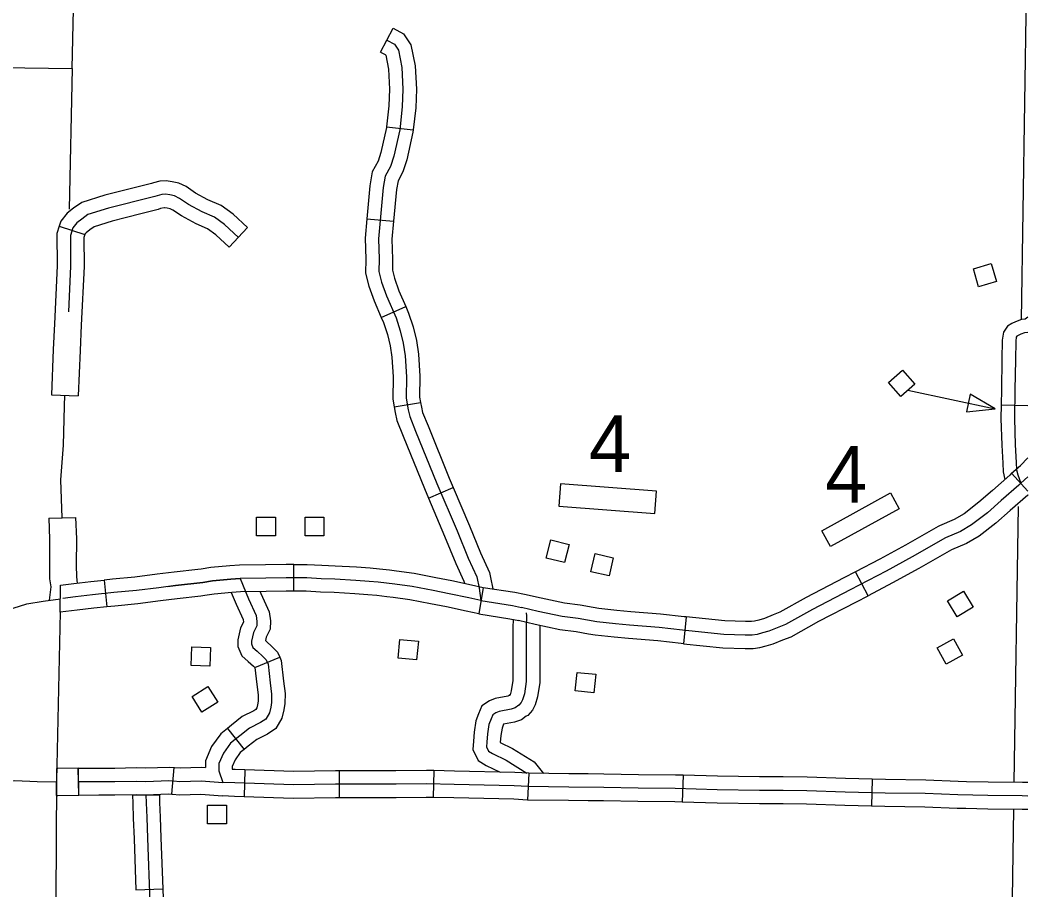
# Model space of a CAD drawing. Extents: x 61396 to 64680, y 55472 to 57605.
# Drawn here: x 63267.3 to 63443.1, y 56178.4 to 56330.1 of the extents above; entities that cross this region are included whole.
import ezdxf

# ---------------------------------------------------------------- set-up
doc = ezdxf.new("R2010")
doc.units = 0
for name, color, linetype in [('31', 7, 'Continuous'), ('32', 7, 'Continuous'), ('33', 7, 'Continuous'), ('34', 7, 'Continuous'), ('45', 7, 'Continuous'), ('5', 7, 'Continuous'), ('56', 7, 'Continuous'), ('57', 7, 'Continuous'), ('6', 7, 'Continuous')]:
    doc.layers.add(name, color=color, linetype=linetype)

msp = doc.modelspace()

# ---------------------------------------------------------------- linework, layer by layer
at = {"layer": '31'}
for p, q in [((63443.15, 56247.92), (63440.32, 56251.03)), ((63315.05, 56230.44), (63315.05, 56235.13)), ((63415.26, 56229.67), (63413.09, 56233.82)), ((63281.97, 56232.39), (63282.43, 56227.72)), ((63348.09, 56231.13), (63347.36, 56226.5)), ((63383.54, 56225.96), (63383.05, 56221.29)), ((63273.64, 56199.51), (63273.6, 56194.82)), ((63277.53, 56194.89), (63277.47, 56199.57)), ((63293.79, 56195.04), (63294.17, 56199.71)), ((63273.6, 56194.82), (63273.6, 56194.82))]:
    msp.add_line(p, q, dxfattribs=at)
for points in [[(63440.32, 56251.03), (63441.84, 56252.4), (63443.15, 56253.71)], [(63440.32, 56251.03), (63439.99, 56250.72), (63436.95, 56248.03), (63434.6, 56245.96), (63432.01, 56243.96), (63430.31, 56242.97), (63427.73, 56241.88), (63427.47, 56241.72)], [(63443.15, 56250.42), (63441.9, 56249.29)], [(63441.9, 56249.29), (63441.56, 56248.98), (63438.5, 56246.27), (63436.09, 56244.15), (63433.32, 56242.02), (63431.37, 56240.87), (63428.78, 56239.77), (63422.97, 56236.44), (63418.42, 56233.96), (63412.14, 56230.68), (63405.58, 56227.29), (63400.86, 56224.64), (63397.93, 56223.49), (63396.83, 56223.17), (63395.91, 56222.92), (63395.05, 56222.8), (63393.83, 56222.81), (63390.1, 56222.92), (63382.91, 56223.67), (63378.82, 56224.13), (63373.64, 56224.53), (63371.17, 56224.76), (63367.94, 56225.1), (63364.66, 56225.68), (63361.9, 56226.02), (63357.7, 56226.94), (63354.81, 56227.62)], [(63443.15, 56247.26), (63443.12, 56247.23), (63440.06, 56244.52), (63437.58, 56242.34), (63434.64, 56240.07), (63432.42, 56238.77), (63429.82, 56237.67), (63429.8, 56237.66)], [(63427.47, 56241.72), (63421.82, 56238.48), (63417.32, 56236.03), (63413.09, 56233.82)], [(63429.8, 56237.66), (63424.11, 56234.39), (63419.52, 56231.9), (63415.26, 56229.67)], [(63315.05, 56235.13), (63313.7, 56235.13), (63310.13, 56235.07), (63305.58, 56235.01), (63303.88, 56234.9), (63300.58, 56234.59), (63298.87, 56234.32), (63298.32, 56234.26)], [(63315.05, 56235.13), (63317.36, 56235.13), (63319.93, 56234.98), (63322.3, 56234.9), (63326.01, 56234.69), (63328.37, 56234.51), (63330, 56234.36), (63331.77, 56234.16)], [(63298.32, 56234.26), (63294.16, 56233.77), (63291.22, 56233.4), (63287.34, 56232.89), (63283.41, 56232.53), (63281.97, 56232.39)], [(63293.03, 56231.26), (63294.44, 56231.44), (63299.19, 56232), (63300.87, 56232.27), (63304.06, 56232.56), (63305.67, 56232.66)], [(63347.72, 56228.81), (63345.6, 56229.27), (63342.17, 56230), (63339.38, 56230.56), (63335.69, 56231.26), (63332.69, 56231.7), (63329.76, 56232.03), (63328.18, 56232.17), (63325.86, 56232.35), (63322.19, 56232.55), (63319.82, 56232.64), (63317.3, 56232.79), (63313.72, 56232.79), (63310.17, 56232.73), (63305.67, 56232.66)], [(63331.77, 56234.16), (63332.99, 56234.03), (63336.08, 56233.58), (63339.83, 56232.86), (63342.64, 56232.3), (63346.09, 56231.56), (63348.09, 56231.13)], [(63413.09, 56233.82), (63411.06, 56232.76), (63404.47, 56229.35), (63399.86, 56226.77), (63398.69, 56226.31)], [(63274.27, 56226.77), (63274.37, 56231.51), (63276.69, 56231.82), (63279.65, 56232.16), (63281.97, 56232.39)], [(63348.09, 56231.13), (63353.62, 56230.26), (63355.29, 56229.91)], [(63298.86, 56229.6), (63294.72, 56229.11), (63291.82, 56228.75), (63287.86, 56228.23), (63283.85, 56227.86), (63282.43, 56227.72)], [(63315.05, 56230.44), (63313.74, 56230.44), (63310.21, 56230.39), (63305.76, 56230.32), (63304.24, 56230.22), (63301.16, 56229.94), (63299.51, 56229.68), (63298.86, 56229.6)], [(63331.26, 56229.5), (63329.53, 56229.69), (63327.98, 56229.84), (63325.71, 56230.01), (63322.09, 56230.21), (63319.71, 56230.3), (63317.23, 56230.44), (63315.05, 56230.44)], [(63347.36, 56226.5), (63345.11, 56226.98), (63341.69, 56227.71), (63338.93, 56228.26), (63335.3, 56228.95), (63332.4, 56229.38), (63331.26, 56229.5)], [(63367.29, 56227.6), (63365.01, 56228), (63362.3, 56228.34), (63358.21, 56229.23), (63355.34, 56229.9)], [(63400.41, 56221.95), (63401.87, 56222.52), (63406.7, 56225.23), (63413.23, 56228.6), (63415.26, 56229.67)], [(63282.43, 56227.72), (63280.15, 56227.5), (63277.27, 56227.17), (63274.27, 56226.77)], [(63347.72, 56228.81), (63353.2, 56227.95), (63354.81, 56227.62)], [(63383.54, 56225.96), (63383.16, 56226), (63379.04, 56226.46), (63373.84, 56226.86), (63371.4, 56227.09), (63368.27, 56227.43), (63367.29, 56227.6)], [(63347.36, 56226.5), (63352.78, 56225.64), (63354.34, 56225.32)], [(63398.69, 56226.31), (63397.17, 56225.71), (63396.19, 56225.43), (63395.44, 56225.22), (63394.9, 56225.15), (63393.87, 56225.15), (63390.26, 56225.26), (63383.54, 56225.96)], [(63366.48, 56222.98), (63364.31, 56223.36), (63361.5, 56223.71), (63357.18, 56224.66), (63354.28, 56225.33)], [(63383.05, 56221.29), (63382.65, 56221.34), (63378.6, 56221.79), (63373.44, 56222.19), (63370.93, 56222.43), (63367.62, 56222.78), (63366.48, 56222.98)], [(63383.05, 56221.29), (63389.95, 56220.58), (63393.79, 56220.47), (63395.2, 56220.46), (63396.39, 56220.62), (63397.47, 56220.92), (63398.69, 56221.27), (63400.41, 56221.95)], [(63277.53, 56194.89), (63277.44, 56199.57), (63273.88, 56199.5), (63273.64, 56199.51)], [(63277.47, 56199.57), (63281.01, 56199.61), (63283.8, 56199.61), (63287.57, 56199.68), (63289.23, 56199.62), (63293.3, 56199.78), (63294.17, 56199.71)], [(63294.17, 56199.71), (63294.26, 56199.7)], [(63289.24, 56197.28), (63293.25, 56197.43), (63294.07, 56197.37)], [(63277.49, 56197.23), (63281.02, 56197.26), (63283.82, 56197.26), (63287.56, 56197.33), (63289.24, 56197.28)], [(63273.6, 56194.82), (63273.9, 56194.82), (63277.53, 56194.89)], [(63277.53, 56194.89), (63281.03, 56194.92), (63283.84, 56194.92), (63287.54, 56194.99), (63289.25, 56194.93), (63293.2, 56195.09), (63293.79, 56195.04)], [(63293.79, 56195.04), (63293.89, 56195.03)]]:
    msp.add_lwpolyline(points, dxfattribs=at)
at = {"layer": '32'}
for p, q in [((63330.2, 56324.51), (63332.37, 56328.67)), ((63331.23, 56311.46), (63335.88, 56310.93)), ((63327.8, 56295.4), (63332.47, 56294.98)), ((63330.3, 56278.23), (63334.6, 56280.1)), ((63332.56, 56262.59), (63337.17, 56263.39)), ((63438.5, 56262.94), (63443.15, 56262.87)), ((63338.56, 56246.68), (63342.87, 56248.52)), ((63308.27, 56217.14), (63312.59, 56218.96)), ((63303.46, 56206.49), (63306.39, 56202.83)), ((63306.53, 56199.29), (63306.37, 56194.6)), ((63339.5, 56199.15), (63339.39, 56194.46)), ((63322.95, 56199.12), (63322.95, 56194.43)), ((63356.06, 56198.71), (63355.82, 56194.03)), ((63286.92, 56194.91), (63291.61, 56194.96)), ((63287.5, 56178.36), (63292.19, 56178.53))]:
    msp.add_line(p, q, dxfattribs=at)
for points in [[(63332.37, 56328.67), (63334.22, 56327.7), (63335.5, 56325.78), (63336.26, 56322.11), (63336.45, 56318.02), (63336.33, 56314.79), (63335.88, 56310.93)], [(63331.28, 56326.59), (63332.61, 56325.9), (63333.3, 56324.86), (63333.93, 56321.81), (63334.1, 56318.02), (63333.99, 56314.97), (63333.53, 56310.94), (63332.49, 56306.34), (63331.91, 56304.55), (63330.99, 56302.83), (63330.65, 56300.87), (63329.84, 56291.95), (63329.96, 56288.39), (63329.9, 56286.2), (63330.36, 56284.36), (63331.22, 56282), (63332.89, 56278.15), (63333.64, 56275.9), (63334.16, 56273.72), (63334.5, 56271.53), (63334.72, 56267.88), (63334.66, 56264.14), (63335.02, 56262.09), (63335.28, 56260.91), (63336.31, 56258.4), (63340, 56249.27), (63343.54, 56240.96), (63345.49, 56236.24), (63346.98, 56232.96), (63347.39, 56230.96), (63347.72, 56228.81)], [(63330.2, 56324.51), (63330.99, 56324.1), (63331.09, 56323.94), (63331.6, 56321.52), (63331.76, 56318.01), (63331.65, 56315.14), (63331.23, 56311.46)], [(63331.23, 56311.46), (63331.21, 56311.33), (63330.23, 56306.96), (63329.75, 56305.47), (63328.75, 56303.6), (63328.32, 56301.18), (63327.8, 56295.4)], [(63335.88, 56310.93), (63335.84, 56310.55), (63334.75, 56305.72), (63334.08, 56303.63), (63333.24, 56302.05), (63332.97, 56300.56), (63332.47, 56294.98)], [(63327.8, 56295.4), (63327.5, 56292.02), (63327.61, 56288.38), (63327.55, 56285.94), (63328.12, 56283.67), (63329.05, 56281.13), (63330.3, 56278.23)], [(63332.47, 56294.98), (63332.19, 56291.89), (63332.3, 56288.39), (63332.25, 56286.46), (63332.6, 56285.05), (63333.4, 56282.87), (63334.6, 56280.1)], [(63334.6, 56280.1), (63335.08, 56278.98), (63335.9, 56276.55), (63336.46, 56274.17), (63336.84, 56271.78), (63337.06, 56267.94), (63337.01, 56264.33), (63337.17, 56263.39)], [(63330.3, 56278.23), (63330.7, 56277.31), (63331.38, 56275.26), (63331.86, 56273.26), (63332.17, 56271.28), (63332.37, 56267.83), (63332.32, 56263.95), (63332.56, 56262.59)], [(63443.15, 56278.26), (63442.7, 56277.91), (63442.04, 56277.86), (63440.98, 56277.45), (63440.35, 56277.13), (63439.59, 56276.71), (63438.87, 56275.64), (63438.68, 56274.23), (63438.63, 56270.86), (63438.54, 56265.65), (63438.5, 56262.94)], [(63443.15, 56275.59), (63442.56, 56275.55), (63441.93, 56275.3), (63441.44, 56275.06), (63441.22, 56274.94), (63441.12, 56274.79), (63441.03, 56274.06), (63440.98, 56270.82), (63440.88, 56265.61), (63440.81, 56260.61), (63440.95, 56256.01), (63441.1, 56252.92), (63441.17, 56251.62), (63441.37, 56250.75), (63441.9, 56249.29)], [(63332.56, 56262.59), (63332.72, 56261.64), (63333.03, 56260.21), (63334.14, 56257.51), (63337.84, 56248.37), (63338.56, 56246.68)], [(63337.17, 56263.39), (63337.32, 56262.54), (63337.53, 56261.61), (63338.48, 56259.28), (63342.17, 56250.17), (63342.87, 56248.52)], [(63438.5, 56262.94), (63438.46, 56260.59), (63438.61, 56255.92), (63438.76, 56252.79), (63438.84, 56251.3), (63439.14, 56249.97)], [(63342.87, 56248.52), (63345.7, 56241.87), (63347.64, 56237.17), (63349.22, 56233.69), (63349.39, 56232.87)], [(63338.56, 56246.68), (63341.38, 56240.05), (63343.34, 56235.31), (63344.73, 56232.23), (63344.82, 56231.83)], [(63305.67, 56232.66), (63307.14, 56229.13), (63308.47, 56226.19), (63308.63, 56225.17), (63308.59, 56224.42), (63308, 56223.24), (63307.65, 56221.71), (63307.65, 56221.28), (63307.92, 56220.61), (63308.67, 56219.98), (63309.65, 56219.08), (63310.24, 56218.49), (63310.56, 56217.74), (63310.91, 56214.48), (63311.19, 56212.48), (63311.15, 56211.06), (63311.03, 56210.2), (63310.79, 56209.22), (63310.16, 56208.16), (63309.26, 56207.53), (63307.33, 56206.59), (63305.65, 56205.23), (63304.01, 56203.92), (63302.76, 56202.22), (63301.98, 56200.38), (63301.98, 56199.14), (63302.69, 56197.08)], [(63349.39, 56232.87), (63349.8, 56230.86)], [(63304.15, 56230.22), (63304.99, 56228.2), (63306.21, 56225.51), (63306.28, 56225.05), (63306.28, 56225.03), (63305.78, 56224.04), (63305.31, 56221.98), (63305.31, 56220.81), (63305.98, 56219.19), (63307.12, 56218.22), (63308.03, 56217.39), (63308.26, 56217.16), (63308.27, 56217.14)], [(63309.16, 56230.37), (63309.29, 56230.07), (63310.74, 56226.86), (63310.98, 56225.28), (63310.91, 56223.81), (63310.22, 56222.44), (63310.09, 56221.85), (63310.22, 56221.74), (63311.28, 56220.77), (63312.22, 56219.82), (63312.59, 56218.96)], [(63312.59, 56218.96), (63312.85, 56218.34), (63313.24, 56214.77), (63313.53, 56212.61), (63313.49, 56210.87), (63313.33, 56209.77), (63312.99, 56208.33), (63311.92, 56206.52), (63310.45, 56205.5), (63308.6, 56204.6), (63307.11, 56203.4), (63306.39, 56202.83)], [(63308.26, 56217.15), (63308.58, 56214.2), (63308.84, 56212.35), (63308.81, 56211.26), (63308.72, 56210.63), (63308.6, 56210.11), (63308.41, 56209.79), (63308.07, 56209.56), (63306.07, 56208.58), (63304.18, 56207.06), (63303.46, 56206.49)], [(63303.46, 56206.49), (63302.3, 56205.56), (63300.71, 56203.39), (63299.63, 56200.87), (63299.63, 56199.69)], [(63306.39, 56202.83), (63305.72, 56202.29), (63304.81, 56201.05), (63304.32, 56199.9), (63304.32, 56199.53), (63304.38, 56199.36)], [(63294.26, 56199.7), (63295.21, 56199.63), (63298.96, 56199.74), (63299.63, 56199.69)], [(63306.53, 56199.29), (63304.85, 56199.34), (63304.38, 56199.36)], [(63322.95, 56199.12), (63322.31, 56199.12), (63315.01, 56199.01), (63306.53, 56199.29)], [(63339.5, 56199.15), (63338.21, 56199.18), (63332.88, 56199.12), (63322.95, 56199.12)], [(63356.06, 56198.71), (63353.6, 56198.84), (63343.1, 56199.06), (63339.5, 56199.15)], [(63294.07, 56197.37), (63295.16, 56197.28), (63298.89, 56197.4), (63302.69, 56197.08)], [(63355.94, 56196.37), (63353.52, 56196.5), (63343.05, 56196.72), (63338.19, 56196.83), (63332.89, 56196.78), (63322.33, 56196.78), (63314.99, 56196.66), (63304.77, 56197), (63302.69, 56197.08)], [(63286.92, 56194.91), (63286.94, 56193.44), (63287.05, 56190.86), (63287.17, 56187.28), (63287.5, 56178.36)], [(63289.26, 56194.93), (63289.28, 56193.51), (63289.4, 56190.95), (63289.51, 56187.37), (63289.93, 56176.23), (63289.97, 56174.85)], [(63291.61, 56194.96), (63291.62, 56193.57), (63291.74, 56191.04), (63291.85, 56187.45), (63292.19, 56178.53)], [(63293.89, 56195.03), (63295.1, 56194.93), (63298.83, 56195.05), (63302.61, 56194.73)], [(63306.37, 56194.6), (63304.69, 56194.66), (63302.61, 56194.73)], [(63322.95, 56194.43), (63322.35, 56194.43), (63314.97, 56194.32), (63306.37, 56194.6)], [(63339.39, 56194.46), (63338.18, 56194.49), (63332.9, 56194.43), (63322.95, 56194.43)], [(63355.82, 56194.03), (63353.43, 56194.15), (63343, 56194.38), (63339.39, 56194.46)], [(63292.19, 56178.53), (63292.32, 56175.12)]]:
    msp.add_lwpolyline(points, dxfattribs=at)
at = {"layer": '33'}
for points in [[(63262.47, 56225.76), (63264.34, 56226.72), (63266.1, 56227.47), (63268.48, 56228.23), (63271.31, 56228.74), (63274.32, 56229.14)], [(63273.62, 56197.16), (63270.26, 56197.2), (63266.39, 56197.36), (63263.43, 56197.33), (63262.83, 56197.6)]]:
    msp.add_lwpolyline(points, dxfattribs=at)
at = {"layer": '34'}
msp.add_lwpolyline([(63274.64, 56243.26), (63274.4, 56249.89), (63274.89, 56255.93), (63275.03, 56262.75), (63275.11, 56264.64)], dxfattribs=at)
at = {"layer": '45'}
for p, q in [((63274.12, 56294.13), (63278.58, 56292.69)), ((63306.98, 56293.88), (63303.79, 56290.45)), ((63272.29, 56243.18), (63276.98, 56243.34)), ((63382.99, 56198.35), (63382.85, 56193.66)), ((63415.97, 56197.65), (63415.85, 56192.97))]:
    msp.add_line(p, q, dxfattribs=at)
for points in [[(63290.57, 56301.7), (63290.21, 56301.6), (63287.42, 56300.91), (63284.43, 56300.13), (63282.09, 56299.53), (63278.06, 56298.28), (63276.64, 56297.25), (63275.53, 56296.38), (63274.4, 56295.01), (63274.12, 56294.13)], [(63306.98, 56293.88), (63304.45, 56296.23), (63302.36, 56297.74), (63300.08, 56298.74), (63297.91, 56299.92), (63296.26, 56301.03), (63294.99, 56301.64), (63293.85, 56301.88), (63292.78, 56302.07), (63291.66, 56302.01), (63290.57, 56301.7)], [(63305.39, 56292.16), (63302.96, 56294.42), (63301.19, 56295.7), (63299.05, 56296.63), (63296.69, 56297.91), (63295.1, 56298.99), (63294.23, 56299.4), (63293.4, 56299.58), (63292.64, 56299.72), (63292.05, 56299.68), (63290.8, 56299.33), (63287.99, 56298.64), (63285.02, 56297.86), (63282.73, 56297.27), (63279.12, 56296.15), (63278.05, 56295.37), (63277.18, 56294.69), (63276.49, 56293.87), (63276.06, 56292.5), (63276.11, 56287.15), (63275.73, 56279.17)], [(63291.82, 56297.19), (63291.4, 56297.07), (63288.57, 56296.37), (63285.61, 56295.59), (63283.37, 56295.02), (63280.19, 56294.03), (63279.46, 56293.5), (63278.82, 56293), (63278.59, 56292.72), (63278.58, 56292.69)], [(63303.79, 56290.45), (63301.47, 56292.6), (63300.02, 56293.65), (63298.02, 56294.52), (63295.47, 56295.91), (63293.93, 56296.95), (63293.47, 56297.17), (63292.95, 56297.28), (63292.49, 56297.36), (63292.43, 56297.36), (63291.82, 56297.19)], [(63274.12, 56294.13), (63273.71, 56292.86), (63273.76, 56287.19), (63273.29, 56277.07)], [(63278.58, 56292.69), (63278.4, 56292.14), (63278.45, 56287.1), (63277.97, 56276.86)], [(63273.29, 56277.07), (63273.08, 56272.64), (63272.77, 56264.73), (63277.45, 56264.55)], [(63277.97, 56276.86), (63277.76, 56272.44), (63277.45, 56264.55)], [(63272.29, 56243.18), (63272.42, 56239.54), (63272.4, 56234.95), (63272.45, 56232.63), (63272.63, 56231.22), (63272.39, 56228.88)], [(63276.98, 56243.34), (63277.11, 56239.61), (63277.09, 56234.99), (63277.13, 56232.98), (63277.27, 56231.88)], [(63305.67, 56232.66), (63304.06, 56232.56), (63300.87, 56232.27), (63299.19, 56232), (63294.44, 56231.44), (63291.52, 56231.07), (63287.6, 56230.56), (63283.63, 56230.2), (63279.9, 56229.83), (63276.98, 56229.49), (63274.77, 56229.2)], [(63315.05, 56232.79), (63313.72, 56232.79), (63310.17, 56232.73), (63305.67, 56232.66)], [(63355.59, 56226.7), (63355.67, 56226.13), (63355.63, 56224.11), (63355.63, 56217.71), (63355.63, 56214.72), (63355.29, 56212.56), (63354.98, 56211.53), (63354.75, 56211.06), (63354.3, 56210.56), (63353.7, 56210.13), (63352.96, 56209.89), (63350.9, 56209.49), (63350.32, 56209.25), (63349.78, 56208.9), (63349.49, 56208.18), (63349.11, 56207.21), (63348.85, 56205.57), (63348.73, 56204.12), (63348.66, 56203.31), (63349.04, 56202.55), (63349.73, 56202.12), (63352.11, 56200.98), (63355.74, 56198.71)], [(63353.32, 56225.53), (63353.28, 56224.13), (63353.28, 56217.71), (63353.28, 56214.9), (63353, 56213.08), (63352.8, 56212.4), (63352.79, 56212.39), (63352.72, 56212.32), (63352.88, 56212.43)], [(63357.97, 56224.49), (63357.97, 56217.71), (63357.97, 56214.54), (63357.58, 56212.04), (63357.17, 56210.66), (63356.7, 56209.72), (63355.87, 56208.8), (63355.62, 56208.63)], [(63352.88, 56212.43), (63352.63, 56212.25), (63352.38, 56212.17), (63350.21, 56211.75), (63349.22, 56211.33), (63347.88, 56210.46), (63347.31, 56209.05), (63346.84, 56207.83), (63346.52, 56205.85), (63346.4, 56204.32), (63346.27, 56202.86), (63347.24, 56200.91), (63348.6, 56200.07), (63351.04, 56198.89)], [(63355.62, 56208.63), (63354.77, 56208.01), (63353.55, 56207.62), (63351.64, 56207.25), (63351.39, 56206.59), (63351.18, 56205.29), (63351.08, 56204.08), (63353.24, 56203.04), (63354.73, 56202.11)], [(63354.73, 56202.11), (63356.98, 56200.7), (63358.6, 56198.68)], [(63366.44, 56198.58), (63363.06, 56198.61), (63356.06, 56198.71)], [(63382.99, 56198.35), (63381.65, 56198.39), (63375.18, 56198.44), (63369.18, 56198.56), (63366.44, 56198.58)], [(63399.41, 56198.05), (63396.34, 56198.05), (63389.01, 56198.16), (63382.99, 56198.35)], [(63415.97, 56197.65), (63411.34, 56197.76), (63404.64, 56197.99), (63400.47, 56198.05), (63399.41, 56198.05)], [(63432.45, 56197.22), (63430.99, 56197.25), (63425.32, 56197.48), (63418.28, 56197.59), (63415.97, 56197.65)], [(63443.15, 56194.72), (63442.18, 56194.74), (63436.18, 56194.8), (63430.91, 56194.91), (63425.25, 56195.14), (63418.23, 56195.25), (63411.27, 56195.42), (63404.59, 56195.65), (63400.45, 56195.7), (63396.32, 56195.7), (63388.96, 56195.82), (63381.6, 56196.04), (63375.15, 56196.1), (63369.14, 56196.21), (63363.03, 56196.27), (63355.94, 56196.37)], [(63443.15, 56197.07), (63442.22, 56197.09), (63436.22, 56197.14), (63432.45, 56197.22)], [(63366.4, 56193.89), (63363, 56193.93), (63355.82, 56194.03)], [(63382.85, 56193.66), (63381.55, 56193.7), (63375.11, 56193.76), (63369.11, 56193.87), (63366.4, 56193.89)], [(63399.41, 56193.36), (63396.3, 56193.36), (63388.91, 56193.47), (63382.85, 56193.66)], [(63415.85, 56192.97), (63411.2, 56193.08), (63404.53, 56193.3), (63400.44, 56193.36), (63399.41, 56193.36)], [(63432.35, 56192.54), (63430.84, 56192.57), (63425.19, 56192.8), (63418.18, 56192.91), (63415.85, 56192.97)], [(63443.15, 56192.38), (63442.15, 56192.4), (63436.14, 56192.46), (63432.35, 56192.54)]]:
    msp.add_lwpolyline(points, dxfattribs=at)
at = {"layer": '5'}
for points in [[(63276.37, 56321.63), (63277.29, 56363.06)], [(63443.15, 56353.67), (63441.97, 56277.82)], [(63441.46, 56245.21), (63440.72, 56197.1)], [(63440.65, 56192.41), (63439.56, 56118.33)]]:
    msp.add_lwpolyline(points, dxfattribs=at)
at = {"layer": '56'}
for points in [[(63434.56, 56283.57), (63433.64, 56286.69), (63436.77, 56287.61), (63437.69, 56284.49)], [(63418.81, 56266.89), (63421.26, 56269.03), (63423.41, 56266.57), (63420.96, 56264.43)], [(63433.08, 56264.84), (63432.42, 56261.72), (63437.43, 56262.29)], [(63408.72, 56238.25), (63407.21, 56240.99), (63419.19, 56247.59), (63420.69, 56244.85)], [(63308.57, 56240.13), (63308.57, 56243.38), (63311.84, 56243.38), (63311.84, 56240.13)], [(63317.03, 56240.13), (63317.03, 56243.38), (63320.29, 56243.38), (63320.29, 56240.13)], [(63359.12, 56236.24), (63359.91, 56239.39), (63363.08, 56238.6), (63362.29, 56235.44)], [(63366.89, 56233.85), (63367.63, 56237.02), (63370.8, 56236.28), (63370.07, 56233.12)], [(63430.8, 56226), (63429.13, 56228.79), (63431.93, 56230.47), (63433.6, 56227.68)], [(63333.24, 56218.78), (63333.55, 56222.02), (63336.79, 56221.71), (63336.49, 56218.47)], [(63431.73, 56219.29), (63428.89, 56217.72), (63427.31, 56220.58), (63430.16, 56222.15)], [(63297.13, 56217.51), (63297.28, 56220.76), (63300.54, 56220.61), (63300.39, 56217.36)], [(63364.15, 56213.06), (63364.49, 56216.3), (63367.74, 56215.96), (63367.39, 56212.72)], [(63299.03, 56209.34), (63297.3, 56212.09), (63300.06, 56213.83), (63301.79, 56211.07)], [(63300.02, 56189.85), (63300.02, 56193.1), (63303.29, 56193.1), (63303.29, 56189.85)]]:
    msp.add_lwpolyline(points, close=True, dxfattribs=at)
msp.add_lwpolyline([(63422.18, 56265.5), (63437.43, 56262.29)], dxfattribs=at)
at = {"layer": '57'}
for p, q in [((63361.57, 56249.17), (63361.28, 56245.28)), ((63378.32, 56247.92), (63361.57, 56249.17)), ((63378.03, 56244.02), (63378.32, 56247.92)), ((63361.28, 56245.28), (63378.03, 56244.02))]:
    msp.add_line(p, q, dxfattribs=at)
at = {"layer": '6'}
for points in [[(63111.69, 56365.39), (63113.03, 56447.45), (63154.14, 56446.93), (63154.66, 56487.99), (63195.62, 56487.51), (63195.25, 56446.41), (63236.35, 56445.9), (63235.89, 56363.64), (63235.14, 56322.23), (63276.37, 56321.63), (63275.83, 56297.13)], [(63274.27, 56226.77), (63273.62, 56197.36)], [(63273.62, 56197.36), (63272.71, 56032.23), (63271.08, 55911.91)]]:
    msp.add_lwpolyline(points, dxfattribs=at)

# ---------------------------------------------------------------- texts
at = {"layer": '56'}
msp.add_text('4', height=9.9, dxfattribs=at).set_placement((63407.78, 56245.91))
at = {"layer": '57'}
msp.add_text('4', height=9.9, dxfattribs=at).set_placement((63366.55, 56251.26))

doc.saveas('drawing.dxf')
